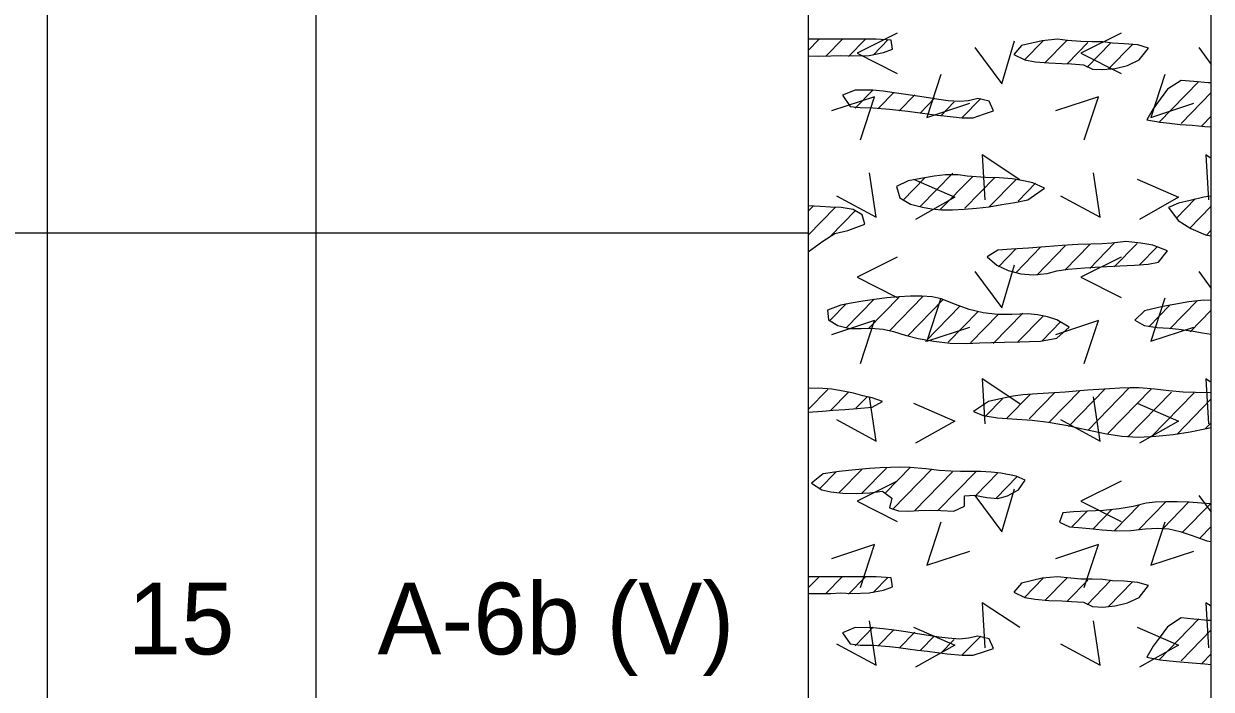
# Model space of a CAD drawing. Extents: x -0.01 to 0.83, y -0.63 to 1.27.
# Drawn here: x 0.7228 to 0.8333, y 0.3881 to 0.45 of the extents above; entities that cross this region are included whole.
import ezdxf

# ---------------------------------------------------------------- set-up
doc = ezdxf.new("R2010")
doc.units = 0

msp = doc.modelspace()

# ---------------------------------------------------------------- linework, layer by layer
for points in [[(0, 0), (0.83333, 0), (0.83333, 1.275), (0, 1.275)], [(0, 0), (0.83333, 0), (0.83333, 1.275), (0, 1.275)], [(0, 0), (0.83333, 0), (0.83333, 1.275), (0, 1.275)], [(0, 0), (0.83333, 0), (0.83333, 1.275), (0, 1.275)], [(0, 0), (0.83333, 0), (0.83333, 1.275), (0, 1.275)], [(0.79583, 0.44696), (0.79676, 0.44695), (0.79792, 0.44697), (0.79882, 0.44701), (0.79992, 0.44697), (0.80151, 0.44701), (0.80282, 0.44727), (0.80367, 0.44759), (0.80354, 0.44843), (0.80216, 0.44851), (0.79583, 0.44851)], [(0.81822, 0.44632), (0.81944, 0.44626), (0.82033, 0.44622), (0.82145, 0.44615), (0.82229, 0.44574), (0.82324, 0.44569), (0.82438, 0.4458), (0.82555, 0.44608), (0.82662, 0.44659), (0.82749, 0.44769), (0.82651, 0.44799), (0.82524, 0.44809), (0.82413, 0.44815), (0.82324, 0.44826), (0.82226, 0.44828), (0.82121, 0.4483), (0.81995, 0.44839), (0.81902, 0.44851), (0.81761, 0.44837), (0.81566, 0.44793), (0.81496, 0.44709), (0.81598, 0.4466), (0.81695, 0.44642)], [(0.83305, 0.44446), (0.83171, 0.44457), (0.83054, 0.44468), (0.82925, 0.44386), (0.82857, 0.44294), (0.82792, 0.44205), (0.82735, 0.44103), (0.82858, 0.4408), (0.82945, 0.4407), (0.83045, 0.4406), (0.83155, 0.44051), (0.83272, 0.44041), (0.83333, 0.44036), (0.83333, 0.44445)], [(0.80066, 0.44216), (0.80188, 0.44215), (0.80339, 0.44202), (0.80423, 0.44193), (0.8051, 0.44182), (0.806, 0.4417), (0.80692, 0.44158), (0.80784, 0.44146), (0.80875, 0.44135), (0.81014, 0.44121), (0.81119, 0.44122), (0.81222, 0.44157), (0.81308, 0.44185), (0.81267, 0.44275), (0.8116, 0.443), (0.81075, 0.4428), (0.80989, 0.44272), (0.80885, 0.4428), (0.80799, 0.44291), (0.80703, 0.44306), (0.806, 0.44322), (0.80492, 0.44339), (0.80384, 0.44354), (0.8028, 0.44368), (0.80182, 0.44377), (0.8002, 0.44378), (0.79901, 0.4433), (0.79974, 0.44226)], [(0.81233, 0.43565), (0.81063, 0.43577), (0.80977, 0.43591), (0.8086, 0.43591), (0.80755, 0.43577), (0.80632, 0.43557), (0.80513, 0.43533), (0.80403, 0.43481), (0.80436, 0.43375), (0.80536, 0.43318), (0.80647, 0.43288), (0.8073, 0.43273), (0.80824, 0.43265), (0.80926, 0.43264), (0.81035, 0.4327), (0.81149, 0.4328), (0.81267, 0.43294), (0.81386, 0.43313), (0.81506, 0.43334), (0.81625, 0.43358), (0.81783, 0.43466), (0.81673, 0.43516), (0.81585, 0.43536), (0.8148, 0.43552), (0.81361, 0.43562)], [(0.83265, 0.43384), (0.83136, 0.43353), (0.83028, 0.43326), (0.82934, 0.43286), (0.83026, 0.43166), (0.83142, 0.4309), (0.83279, 0.43032), (0.83333, 0.43022), (0.83333, 0.43393)], [(0.79583, 0.42875), (0.79719, 0.42974), (0.79831, 0.43044), (0.79951, 0.43071), (0.80111, 0.43131), (0.80086, 0.43219), (0.80002, 0.43267), (0.79889, 0.43286), (0.79791, 0.43289), (0.79694, 0.43295), (0.79583, 0.43303)], [(0.82537, 0.42969), (0.82408, 0.42954), (0.82319, 0.42948), (0.82214, 0.42946), (0.82091, 0.42942), (0.81947, 0.42933), (0.81792, 0.42921), (0.81632, 0.42909), (0.81475, 0.429), (0.81348, 0.42889), (0.81247, 0.42826), (0.81337, 0.42749), (0.81444, 0.42699), (0.81561, 0.4267), (0.81675, 0.4266), (0.81807, 0.42671), (0.81896, 0.42698), (0.82003, 0.42713), (0.82157, 0.42725), (0.82253, 0.42731), (0.82362, 0.42737), (0.82483, 0.42743), (0.82618, 0.42749), (0.82745, 0.4276), (0.82842, 0.42778), (0.82927, 0.42883), (0.82791, 0.42935), (0.82679, 0.42955)], [(0.79885, 0.42378), (0.79763, 0.42332), (0.79773, 0.42242), (0.79859, 0.4219), (0.7997, 0.4216), (0.80074, 0.42161), (0.80165, 0.42163), (0.80281, 0.42154), (0.80377, 0.42134), (0.80486, 0.42099), (0.80606, 0.42069), (0.80751, 0.42042), (0.80905, 0.42023), (0.81052, 0.4202), (0.81177, 0.42026), (0.81289, 0.4203), (0.81408, 0.42033), (0.81553, 0.42037), (0.81642, 0.4204), (0.81745, 0.42043), (0.81897, 0.4207), (0.82011, 0.42174), (0.81896, 0.42241), (0.8181, 0.42268), (0.81717, 0.42287), (0.81626, 0.42298), (0.81479, 0.42292), (0.81343, 0.42292), (0.8121, 0.42307), (0.8108, 0.42337), (0.80953, 0.42384), (0.8082, 0.42438), (0.80736, 0.42454), (0.8064, 0.42462), (0.80536, 0.42462), (0.80427, 0.42456), (0.80314, 0.42445), (0.80201, 0.42431), (0.8009, 0.42414), (0.79984, 0.42396)], [(0.83263, 0.42423), (0.83126, 0.42409), (0.82969, 0.42382), (0.82883, 0.42365), (0.82712, 0.42324), (0.82623, 0.42237), (0.82708, 0.42188), (0.82831, 0.42169), (0.82941, 0.42163), (0.83033, 0.42154), (0.83165, 0.42135), (0.83253, 0.42121), (0.83333, 0.42107), (0.83333, 0.42422)], [(0.79583, 0.41382), (0.79715, 0.41393), (0.79814, 0.41401), (0.79922, 0.41408), (0.80039, 0.41417), (0.80179, 0.41429), (0.80275, 0.41481), (0.80179, 0.41515), (0.80091, 0.41536), (0.80003, 0.41558), (0.79909, 0.41579), (0.79803, 0.41595), (0.79677, 0.41605), (0.79583, 0.41603)], [(0.82816, 0.41158), (0.82978, 0.41174), (0.83137, 0.412), (0.8329, 0.41231), (0.83333, 0.41241), (0.83333, 0.41565), (0.83295, 0.41562), (0.83188, 0.41564), (0.83071, 0.41569), (0.82938, 0.4158), (0.82807, 0.41597), (0.82662, 0.41609), (0.82576, 0.41609), (0.82484, 0.41606), (0.82387, 0.41601), (0.82286, 0.41594), (0.82182, 0.41586), (0.82077, 0.41578), (0.81973, 0.41569), (0.81872, 0.41562), (0.81715, 0.41552), (0.81579, 0.41543), (0.81491, 0.4153), (0.81357, 0.41502), (0.8126, 0.41481), (0.81121, 0.41389), (0.8121, 0.41353), (0.81345, 0.41329), (0.81479, 0.41319), (0.81668, 0.41309), (0.81818, 0.41289), (0.81905, 0.41275), (0.82, 0.41257), (0.82107, 0.41235), (0.82225, 0.4121), (0.82357, 0.41181), (0.82501, 0.41158), (0.82656, 0.41151)], [(0.79708, 0.40659), (0.79794, 0.40642), (0.79904, 0.4063), (0.80028, 0.40627), (0.80156, 0.40632), (0.80274, 0.40648), (0.80361, 0.40582), (0.80338, 0.40492), (0.80422, 0.40465), (0.80517, 0.40463), (0.80613, 0.40469), (0.8072, 0.40472), (0.80818, 0.40469), (0.80939, 0.40461), (0.81037, 0.40508), (0.81038, 0.40603), (0.8113, 0.40609), (0.81244, 0.4059), (0.81346, 0.40579), (0.81438, 0.40605), (0.81539, 0.40659), (0.81601, 0.40751), (0.81517, 0.40788), (0.81374, 0.40815), (0.81285, 0.40825), (0.81187, 0.40831), (0.81, 0.40831), (0.8091, 0.40833), (0.808, 0.4084), (0.80678, 0.40856), (0.8053, 0.40869), (0.80443, 0.4087), (0.80349, 0.40868), (0.80251, 0.40864), (0.80152, 0.40858), (0.80054, 0.4085), (0.79959, 0.40841), (0.7987, 0.40831), (0.79722, 0.40809), (0.79614, 0.40721)], [(0.83241, 0.40537), (0.83129, 0.40544), (0.83017, 0.40548), (0.8291, 0.40548), (0.82811, 0.40544), (0.82728, 0.40535), (0.82608, 0.40505), (0.82476, 0.40483), (0.8233, 0.40469), (0.82183, 0.40461), (0.82051, 0.40455), (0.81951, 0.40445), (0.81922, 0.40358), (0.82013, 0.40317), (0.82097, 0.40311), (0.822, 0.40301), (0.82318, 0.40288), (0.82448, 0.4028), (0.82584, 0.40282), (0.82719, 0.40298), (0.82836, 0.40305), (0.8294, 0.40297), (0.83043, 0.40274), (0.83156, 0.40235), (0.83291, 0.40186), (0.83333, 0.40178), (0.83333, 0.4053)], [(0.79583, 0.39696), (0.79676, 0.39695), (0.79792, 0.39697), (0.79882, 0.39701), (0.79992, 0.39697), (0.80151, 0.39701), (0.80282, 0.39727), (0.80367, 0.39759), (0.80354, 0.39843), (0.80216, 0.39851), (0.79583, 0.39851)], [(0.81822, 0.39632), (0.81944, 0.39626), (0.82033, 0.39622), (0.82145, 0.39615), (0.82229, 0.39574), (0.82324, 0.39569), (0.82438, 0.3958), (0.82555, 0.39609), (0.82662, 0.39659), (0.82749, 0.39769), (0.82651, 0.39799), (0.82524, 0.39809), (0.82413, 0.39815), (0.82324, 0.39826), (0.82226, 0.39828), (0.82121, 0.3983), (0.81995, 0.3984), (0.81902, 0.39851), (0.81761, 0.39837), (0.81566, 0.39793), (0.81496, 0.39709), (0.81598, 0.3966), (0.81695, 0.39642)], [(0.83305, 0.39446), (0.83171, 0.39457), (0.83054, 0.39468), (0.82925, 0.39386), (0.82857, 0.39294), (0.82792, 0.39205), (0.82735, 0.39103), (0.82858, 0.3908), (0.82945, 0.3907), (0.83045, 0.3906), (0.83155, 0.39051), (0.83272, 0.39041), (0.83333, 0.39036), (0.83333, 0.39445)], [(0.80066, 0.39216), (0.80188, 0.39215), (0.80339, 0.39202), (0.80423, 0.39193), (0.8051, 0.39182), (0.806, 0.3917), (0.80692, 0.39158), (0.80784, 0.39146), (0.80875, 0.39135), (0.81014, 0.39121), (0.81119, 0.39122), (0.81222, 0.39157), (0.81308, 0.39185), (0.81267, 0.39275), (0.8116, 0.393), (0.81075, 0.3928), (0.80989, 0.39272), (0.80885, 0.3928), (0.80799, 0.39291), (0.80703, 0.39306), (0.806, 0.39322), (0.80492, 0.39339), (0.80384, 0.39354), (0.8028, 0.39368), (0.80182, 0.39377), (0.8002, 0.39378), (0.79901, 0.3933), (0.79974, 0.39226)]]:
    msp.add_lwpolyline(points, close=True)
for points in [[(0.725, 1.22083), (0.725, -0.62183)], [(0.75, 1.22083), (0.75, -0.62183)], [(0.75, 1.22083), (0.75, -0.62183)], [(0.79583, 1.22083), (0.79583, -0.62183)], [(0.725, 1.20833), (0.725, -0.62183)], [(0.83333, -0.62183), (0.83333, 1.13843)], [(0.80412, 0.44908), (0.80038, 0.44721), (0.80412, 0.44533)], [(0.82496, 0.44908), (0.82121, 0.44721), (0.82496, 0.44533)], [(0.79583, 0.44748), (0.79681, 0.44848)], [(0.79898, 0.4485), (0.79747, 0.44695)], [(0.80116, 0.44852), (0.79959, 0.44691)], [(0.80328, 0.44848), (0.80188, 0.44704)], [(0.81134, 0.44774), (0.81384, 0.44436), (0.81503, 0.44836)], [(0.8177, 0.44837), (0.81596, 0.44659)], [(0.81988, 0.44839), (0.81785, 0.44632)], [(0.82185, 0.4482), (0.81997, 0.44627)], [(0.824, 0.44819), (0.82178, 0.44591)], [(0.82601, 0.44803), (0.82378, 0.44575)], [(0.83217, 0.44774), (0.83333, 0.44618)], [(0.80818, 0.44525), (0.80687, 0.44125), (0.81087, 0.44256)], [(0.82901, 0.44525), (0.8277, 0.44125), (0.8317, 0.44256)], [(0.83217, 0.44459), (0.82844, 0.44077)], [(0.80069, 0.43917), (0.802, 0.44317), (0.798, 0.44186)], [(0.80188, 0.44381), (0.8002, 0.44209)], [(0.8038, 0.44357), (0.80237, 0.44211)], [(0.80575, 0.44335), (0.80429, 0.44186)], [(0.82152, 0.43917), (0.82284, 0.44317), (0.81884, 0.44186)], [(0.83333, 0.44357), (0.83052, 0.44069)], [(0.80758, 0.44302), (0.80627, 0.44168)], [(0.80941, 0.44269), (0.80816, 0.4414)], [(0.81188, 0.443), (0.81016, 0.44124)], [(0.83333, 0.44136), (0.83245, 0.44045)], [(0.81551, 0.43544), (0.81201, 0.43776), (0.81226, 0.43357)], [(0.83333, 0.43743), (0.83284, 0.43776), (0.83309, 0.43357)], [(0.79847, 0.43396), (0.80215, 0.43196), (0.80153, 0.43609)], [(0.80465, 0.43354), (0.80667, 0.43561)], [(0.80562, 0.43551), (0.80946, 0.43382), (0.80581, 0.43176)], [(0.80626, 0.43297), (0.80928, 0.43607)], [(0.80809, 0.43264), (0.81111, 0.43573)], [(0.81041, 0.4328), (0.81318, 0.43564)], [(0.81264, 0.43288), (0.81518, 0.43548)], [(0.8193, 0.43396), (0.82299, 0.43196), (0.82236, 0.43609)], [(0.82645, 0.43551), (0.83029, 0.43382), (0.82664, 0.43176)], [(0.81536, 0.43345), (0.81699, 0.43512)], [(0.8301, 0.43188), (0.83184, 0.43366)], [(0.7963, 0.43299), (0.79583, 0.43251)], [(0.79834, 0.43286), (0.79583, 0.4303)], [(0.79786, 0.43016), (0.80023, 0.43259)], [(0.83131, 0.4309), (0.83333, 0.43298)], [(0.70417, 0.4305), (0.725, 0.4305)], [(0.725, 0.4305), (0.75, 0.4305)], [(0.75, 0.4305), (0.79583, 0.4305)], [(0.83285, 0.43027), (0.83333, 0.43076)], [(0.81519, 0.42906), (0.81354, 0.42736)], [(0.81514, 0.4268), (0.81748, 0.42919)], [(0.81709, 0.42658), (0.81974, 0.4293)], [(0.8197, 0.42704), (0.82203, 0.42943)], [(0.82202, 0.4272), (0.8243, 0.42954)], [(0.82431, 0.42733), (0.82644, 0.42953)], [(0.82663, 0.4275), (0.82834, 0.42925)], [(0.80412, 0.42825), (0.80038, 0.42637), (0.80412, 0.4245)], [(0.82496, 0.42825), (0.82121, 0.42637), (0.82496, 0.4245)], [(0.81134, 0.42691), (0.81384, 0.42353), (0.81503, 0.42753)], [(0.83217, 0.42691), (0.83333, 0.42534)], [(0.79933, 0.42165), (0.80195, 0.42434)], [(0.80142, 0.42158), (0.8043, 0.42453)], [(0.80653, 0.42461), (0.8034, 0.4214)], [(0.80818, 0.42442), (0.80687, 0.42042), (0.81087, 0.42173)], [(0.82901, 0.42442), (0.8277, 0.42042), (0.8317, 0.42173)], [(0.79938, 0.42392), (0.79786, 0.42237)], [(0.80506, 0.42089), (0.8084, 0.42431)], [(0.80997, 0.42371), (0.80675, 0.4204)], [(0.82751, 0.42176), (0.82945, 0.42375)], [(0.83203, 0.42417), (0.82949, 0.42157)], [(0.83138, 0.4213), (0.83333, 0.4233)], [(0.80069, 0.41834), (0.802, 0.42234), (0.798, 0.42102)], [(0.81164, 0.4232), (0.80884, 0.42034)], [(0.81353, 0.42293), (0.81094, 0.42027)], [(0.81303, 0.42021), (0.81579, 0.42303)], [(0.81534, 0.42036), (0.81768, 0.42276)], [(0.8176, 0.42047), (0.81934, 0.42225)], [(0.82152, 0.41834), (0.82284, 0.42234), (0.81884, 0.42102)], [(0.83333, 0.42108), (0.83333, 0.42109)], [(0.81551, 0.41461), (0.81201, 0.41692), (0.81226, 0.41273)], [(0.83333, 0.4166), (0.83284, 0.41692), (0.83309, 0.41273)], [(0.79765, 0.41594), (0.79583, 0.41407)], [(0.7996, 0.41572), (0.79786, 0.41394)], [(0.8143, 0.41326), (0.8165, 0.41551)], [(0.8164, 0.41319), (0.81879, 0.41565)], [(0.81829, 0.41292), (0.82114, 0.41584)], [(0.82004, 0.4125), (0.82346, 0.416)], [(0.82569, 0.41608), (0.82184, 0.41213)], [(0.82775, 0.41598), (0.8237, 0.41183)], [(0.82964, 0.4157), (0.82557, 0.41152)], [(0.83173, 0.41563), (0.82774, 0.41154)], [(0.79847, 0.41313), (0.80215, 0.41113), (0.80153, 0.41525)], [(0.8013, 0.41524), (0.80027, 0.41419)], [(0.80562, 0.41467), (0.80946, 0.41299), (0.80581, 0.41093)], [(0.81392, 0.41508), (0.81235, 0.41348)], [(0.8193, 0.41313), (0.82299, 0.41113), (0.82236, 0.41525)], [(0.82645, 0.41467), (0.83029, 0.41299), (0.82664, 0.41093)], [(0.83333, 0.41506), (0.83012, 0.41176)], [(0.83281, 0.41231), (0.83333, 0.41284)], [(0.79844, 0.40828), (0.79691, 0.40671)], [(0.79871, 0.40634), (0.80085, 0.40853)], [(0.80083, 0.40629), (0.80311, 0.40863)], [(0.80534, 0.40871), (0.80299, 0.40629)], [(0.80367, 0.40478), (0.80732, 0.40852)], [(0.80571, 0.40466), (0.80924, 0.40828)], [(0.81142, 0.40829), (0.80785, 0.40464)], [(0.81141, 0.40607), (0.81348, 0.40819)], [(0.81528, 0.40783), (0.81331, 0.40581)], [(0.80412, 0.40741), (0.80038, 0.40554), (0.80412, 0.40366)], [(0.81134, 0.40607), (0.81384, 0.4027), (0.81503, 0.4067)], [(0.82496, 0.40741), (0.82121, 0.40554), (0.82496, 0.40366)], [(0.83217, 0.40607), (0.83333, 0.40451)], [(0.82035, 0.40315), (0.82176, 0.4046)], [(0.82233, 0.40298), (0.82408, 0.40476)], [(0.82433, 0.40281), (0.82666, 0.4052)], [(0.82909, 0.40548), (0.82656, 0.40289)], [(0.82885, 0.40301), (0.83122, 0.40544)], [(0.83325, 0.40531), (0.83065, 0.40265)], [(0.80818, 0.40358), (0.80687, 0.39958), (0.81087, 0.40089)], [(0.82901, 0.40358), (0.8277, 0.39958), (0.8317, 0.40089)], [(0.83333, 0.40318), (0.83227, 0.40209)], [(0.80069, 0.3975), (0.802, 0.4015), (0.798, 0.40019)], [(0.82152, 0.3975), (0.82284, 0.4015), (0.81884, 0.40019)], [(0.79583, 0.39748), (0.79681, 0.39848)], [(0.79898, 0.3985), (0.79747, 0.39695)], [(0.80116, 0.39852), (0.79959, 0.39691)], [(0.80328, 0.39848), (0.80188, 0.39704)], [(0.8177, 0.39837), (0.81596, 0.39659)], [(0.81988, 0.39839), (0.81785, 0.39632)], [(0.82185, 0.3982), (0.81997, 0.39627)], [(0.824, 0.39819), (0.82178, 0.39591)], [(0.82601, 0.39803), (0.82378, 0.39575)], [(0.81551, 0.39378), (0.81201, 0.39609), (0.81226, 0.3919)], [(0.83333, 0.39577), (0.83284, 0.39609), (0.83309, 0.3919)], [(0.83217, 0.39459), (0.82844, 0.39077)], [(0.79847, 0.39229), (0.80215, 0.39029), (0.80153, 0.39442)], [(0.80188, 0.39381), (0.8002, 0.39209)], [(0.8038, 0.39357), (0.80237, 0.39211)], [(0.80562, 0.39384), (0.80946, 0.39216), (0.80581, 0.39009)], [(0.8193, 0.39229), (0.82299, 0.39029), (0.82236, 0.39442)], [(0.82645, 0.39384), (0.83029, 0.39216), (0.82664, 0.39009)], [(0.83333, 0.39357), (0.83052, 0.39069)], [(0.80575, 0.39335), (0.80429, 0.39186)], [(0.80758, 0.39302), (0.80627, 0.39168)], [(0.80941, 0.39269), (0.80816, 0.3914)], [(0.81188, 0.393), (0.81016, 0.39124)], [(0.83333, 0.39136), (0.83245, 0.39045)]]:
    msp.add_lwpolyline(points)

# ---------------------------------------------------------------- texts
for s, p in [('15', (0.73251, 0.39129)), ('A-6b (V)', (0.75575, 0.39129))]:
    msp.add_text(s, height=0.006667).set_placement(p)

doc.saveas('drawing.dxf')
